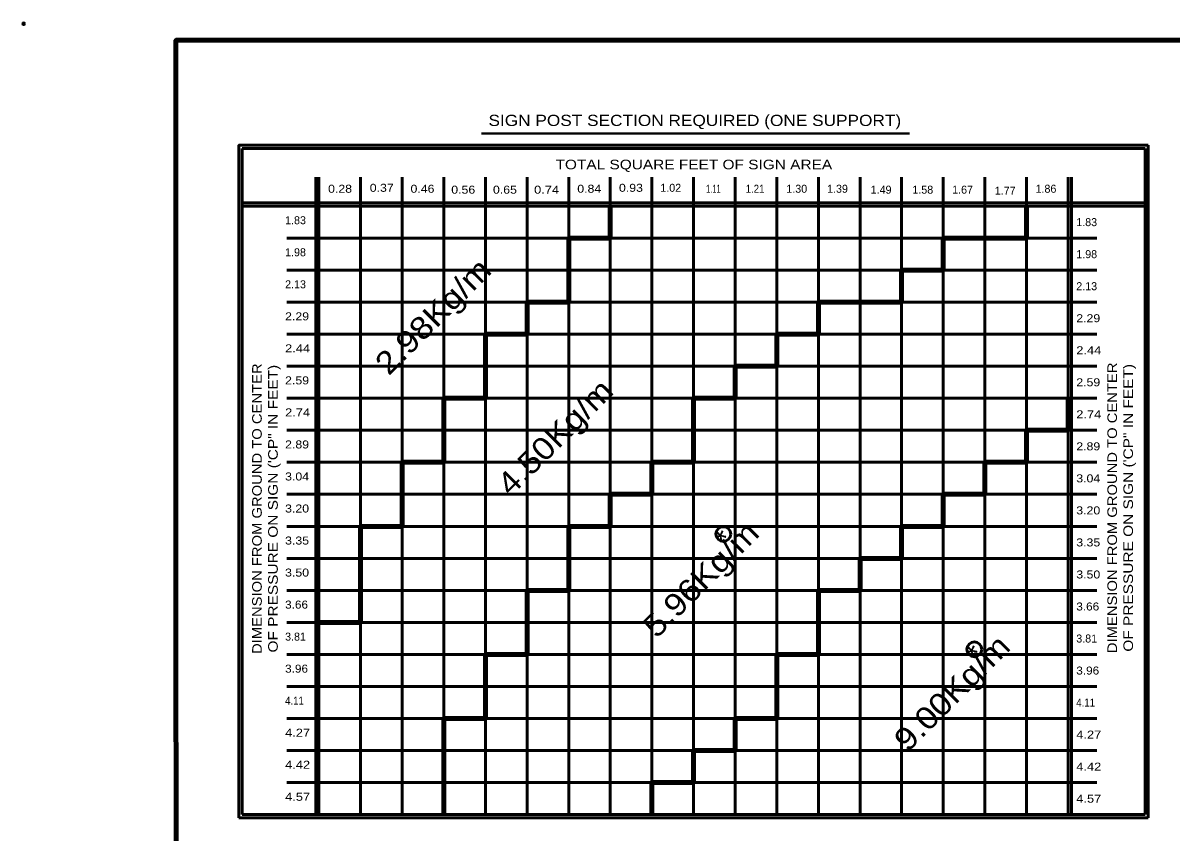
# Model space of a CAD drawing. Extents: x -39 to 816, y -2 to 542.
# Drawn here: x -39.3 to 390.9, y 239.3 to 542.4 of the extents above; entities that cross this region are included whole.
import ezdxf
from ezdxf.enums import TextEntityAlignment as Align

# ---------------------------------------------------------------- set-up
doc = ezdxf.new("R2010")
doc.units = 0
doc.header["$LTSCALE"] = 1.2
doc.header["$PDMODE"] = 32
doc.header["$PDSIZE"] = 0.6
doc.layers.add('1', color=7, linetype='Continuous', lineweight=53)

msp = doc.modelspace()

# ---------------------------------------------------------------- linework, layer by layer
at = {"layer": '1', "lineweight": 40}
msp.add_line((132.557, 500.998), (292.88, 500.998), dxfattribs=at)
at = {"layer": '1'}
for p, q in [((42.794, 495.432), (42.794, 245.832)), ((381.194, 495.432), (42.794, 495.432)), ((381.194, 245.832), (381.194, 495.432)), ((382.394, 244.632), (382.394, 496.632)), ((70.394, 484.632), (70.394, 245.832)), ((71.594, 484.632), (71.594, 245.832)), ((87.194, 484.632), (87.194, 475.032)), ((102.794, 484.632), (102.794, 377.832)), ((118.394, 484.632), (118.394, 401.832)), ((133.994, 484.632), (133.994, 425.832)), ((149.594, 484.632), (149.594, 437.832)), ((165.194, 484.632), (165.194, 461.832)), ((180.793, 484.632), (180.793, 473.832)), ((196.394, 484.632), (196.394, 377.832)), ((211.994, 484.632), (211.994, 401.832)), ((227.594, 484.632), (227.594, 413.832)), ((243.194, 484.632), (243.194, 425.832)), ((258.793, 484.632), (258.793, 437.832)), ((274.394, 484.632), (274.394, 341.832)), ((289.994, 484.632), (289.994, 449.832)), ((305.594, 484.632), (305.594, 461.832)), ((321.194, 484.632), (321.194, 377.832)), ((336.793, 484.632), (336.793, 473.832)), ((352.394, 401.832), (352.394, 484.632)), ((353.594, 245.832), (353.594, 484.632)), ((381.194, 475.032), (42.794, 475.032)), ((381.194, 473.832), (42.794, 473.832)), ((87.194, 475.032), (87.194, 353.832)), ((59.594, 461.832), (70.394, 461.832)), ((70.394, 461.832), (165.194, 461.832)), ((180.793, 461.832), (305.594, 461.832)), ((180.793, 461.832), (180.793, 365.832)), ((336.793, 461.832), (363.194, 461.832)), ((336.793, 461.832), (336.793, 389.832)), ((59.594, 449.832), (289.994, 449.832)), ((305.594, 449.832), (363.194, 449.832)), ((305.594, 449.832), (305.594, 365.832)), ((59.594, 437.832), (149.594, 437.832)), ((165.194, 437.832), (258.793, 437.832)), ((165.194, 437.832), (165.194, 353.832)), ((289.994, 437.832), (363.194, 437.832)), ((289.994, 437.832), (289.994, 353.832)), ((59.594, 425.832), (133.994, 425.832)), ((149.594, 425.832), (243.194, 425.832)), ((149.594, 425.832), (149.594, 329.832)), ((258.793, 425.832), (363.194, 425.832)), ((258.793, 425.832), (258.793, 329.832)), ((59.594, 413.832), (227.594, 413.832)), ((243.194, 413.832), (363.194, 413.832)), ((243.194, 413.832), (243.194, 305.832)), ((59.594, 401.832), (118.394, 401.832)), ((133.994, 401.832), (211.994, 401.832)), ((133.994, 401.832), (133.994, 305.832)), ((227.594, 401.832), (363.194, 401.832)), ((227.594, 401.832), (227.594, 281.832)), ((59.594, 389.832), (336.793, 389.832)), ((352.394, 245.832), (352.394, 389.832)), ((352.394, 389.832), (363.194, 389.832)), ((59.594, 377.832), (102.794, 377.832)), ((118.394, 377.832), (196.394, 377.832)), ((118.394, 377.832), (118.394, 281.832)), ((211.994, 377.832), (321.194, 377.832)), ((211.994, 377.832), (211.994, 269.832)), ((336.793, 377.832), (336.793, 245.832)), ((59.594, 365.832), (180.793, 365.832)), ((196.394, 365.832), (305.594, 365.832)), ((196.394, 365.832), (196.394, 257.832)), ((321.194, 365.832), (321.194, 245.832)), ((321.194, 365.832), (363.194, 365.832)), ((59.594, 353.832), (71.594, 353.832)), ((71.594, 353.832), (87.194, 353.832)), ((102.794, 353.832), (102.794, 245.832)), ((102.794, 353.832), (165.194, 353.832)), ((180.793, 353.832), (180.793, 245.832)), ((180.793, 353.832), (289.994, 353.832)), ((305.594, 353.832), (305.594, 245.832)), ((305.594, 353.832), (363.194, 353.832)), ((59.594, 341.832), (274.394, 341.832)), ((289.994, 341.832), (289.994, 245.832)), ((289.994, 341.832), (363.194, 341.832)), ((59.594, 329.832), (149.594, 329.832)), ((165.194, 329.832), (165.194, 245.832)), ((165.194, 329.832), (258.793, 329.832)), ((274.394, 329.832), (274.394, 245.832)), ((274.394, 329.832), (363.194, 329.832)), ((59.594, 317.832), (71.594, 317.832)), ((87.194, 317.832), (363.194, 317.832)), ((87.194, 317.832), (87.194, 245.832)), ((59.594, 305.832), (133.994, 305.832)), ((149.594, 305.832), (149.594, 245.832)), ((149.594, 305.832), (243.194, 305.832)), ((258.793, 305.832), (258.793, 245.832)), ((258.793, 305.832), (363.194, 305.832)), ((59.594, 293.832), (363.194, 293.832)), ((59.594, 281.832), (118.394, 281.832)), ((133.994, 281.832), (133.994, 245.832)), ((133.994, 281.832), (227.594, 281.832)), ((243.194, 281.832), (243.194, 245.832)), ((243.194, 281.832), (363.194, 281.832)), ((59.594, 269.832), (211.994, 269.832)), ((227.594, 269.832), (227.594, 245.832)), ((227.594, 269.832), (363.194, 269.832)), ((59.594, 257.832), (196.394, 257.832)), ((211.994, 257.832), (211.994, 245.832)), ((211.994, 257.832), (363.194, 257.832)), ((42.794, 245.832), (381.194, 245.832)), ((41.593, 244.632), (382.394, 244.632))]:
    msp.add_line(p, q, dxfattribs=at)
at = {"layer": '1', "lineweight": 200}
for p, q in [((180.793, 473.832), (180.793, 461.832)), ((336.793, 473.832), (336.793, 461.832)), ((165.194, 461.832), (165.194, 437.832)), ((165.194, 461.832), (180.793, 461.832)), ((305.594, 461.832), (336.793, 461.832)), ((305.594, 461.832), (305.594, 449.832)), ((289.994, 449.832), (305.594, 449.832)), ((289.994, 449.832), (289.994, 437.832)), ((149.594, 437.832), (149.594, 425.832)), ((149.594, 437.832), (165.194, 437.832)), ((258.793, 437.832), (289.994, 437.832)), ((258.793, 437.832), (258.793, 425.832)), ((133.994, 425.832), (133.994, 401.832)), ((133.994, 425.832), (149.594, 425.832)), ((243.194, 425.832), (258.793, 425.832)), ((243.194, 425.832), (243.194, 413.832)), ((227.594, 413.832), (243.194, 413.832)), ((227.594, 413.832), (227.594, 401.832)), ((118.394, 401.832), (118.394, 377.832)), ((118.394, 401.832), (133.994, 401.832)), ((211.994, 401.832), (227.594, 401.832)), ((211.994, 401.832), (211.994, 377.832)), ((352.394, 389.832), (352.394, 401.832)), ((336.793, 389.832), (352.394, 389.832)), ((336.793, 389.832), (336.793, 377.832)), ((102.794, 377.832), (118.394, 377.832)), ((102.794, 377.832), (102.794, 353.832)), ((196.394, 377.832), (211.994, 377.832)), ((196.394, 377.832), (196.394, 365.832)), ((321.194, 377.832), (336.793, 377.832)), ((321.194, 377.832), (321.194, 365.832)), ((180.793, 365.832), (196.394, 365.832)), ((180.793, 365.832), (180.793, 353.832)), ((305.594, 365.832), (321.194, 365.832)), ((305.594, 365.832), (305.594, 353.832)), ((87.194, 353.832), (87.194, 317.832)), ((87.194, 353.832), (102.794, 353.832)), ((165.194, 353.832), (180.793, 353.832)), ((165.194, 353.832), (165.194, 329.832)), ((289.994, 353.832), (305.594, 353.832)), ((289.994, 353.832), (289.994, 341.832)), ((274.394, 341.832), (289.994, 341.832)), ((274.394, 341.832), (274.394, 329.832)), ((149.594, 329.832), (165.194, 329.832)), ((149.594, 329.832), (149.594, 305.832)), ((258.793, 329.832), (274.394, 329.832)), ((258.793, 329.832), (258.793, 305.832)), ((71.594, 317.832), (87.194, 317.832)), ((133.994, 305.832), (149.594, 305.832)), ((133.994, 305.832), (133.994, 281.832)), ((243.194, 305.832), (258.793, 305.832)), ((243.194, 305.832), (243.194, 281.832)), ((118.394, 281.832), (133.994, 281.832)), ((118.394, 281.832), (118.394, 245.832)), ((227.594, 281.832), (243.194, 281.832)), ((227.594, 281.832), (227.594, 269.832)), ((211.994, 269.832), (227.594, 269.832)), ((211.994, 269.832), (211.994, 257.832)), ((196.394, 257.832), (196.394, 245.832)), ((196.394, 257.832), (211.994, 257.832))]:
    msp.add_line(p, q, dxfattribs=at)
at = {"layer": '1', "lineweight": 158}
msp.add_lwpolyline([(809.673, 536.027), (17.973, 535.927), (18.073, 9.927)], dxfattribs=at)
at = {"layer": '1'}
for points in [[(382.394, 496.632), (41.593, 496.632), (41.593, 244.632)], [(336.793, 377.832), (353.594, 377.832), (363.194, 377.832)]]:
    msp.add_lwpolyline(points, dxfattribs=at)
for centre in [(223.176, 350.937), (317.238, 307.739)]:
    msp.add_circle(centre, 2.772, dxfattribs=at)
msp.add_point((-39.027, 542.127), dxfattribs=at)

# ---------------------------------------------------------------- texts
for s, height, width, p in [('SIGN POST SECTION REQUIRED (ONE SUPPORT)', 4.2, 1.15, (212.466, 503.828)), ('TOTAL SQUARE FEET OF SIGN AREA', 3.6, 1.2, (212.105, 487.599)), ('0.37', 3, 1.15, (95.138, 479.173)), ('0.93', 3, 1.15, (188.532, 479.173)), ('0.28', 3, 1.15, (79.513, 478.818)), ('0.46', 3, 1.15, (110.408, 478.818)), ('0.56', 3, 1.15, (125.678, 478.463)), ('0.65', 3, 1.15, (141.303, 478.463)), ('0.74', 3, 1.2, (156.928, 478.463)), ('0.84', 3, 1.15, (172.908, 478.818)), ('1.11', 3, 0.7, (219.427, 478.818)), ('1.21', 3, 0.9, (235.052, 478.818))]:
    msp.add_text(s, height=height, dxfattribs=dict(at, width=width)).set_placement(p, align=Align.CENTER)
for s, p in [('1.02', (203.447, 479.173)), ('1.30', (250.677, 478.818)), ('1.39', (265.947, 478.818)), ('1.49', (282.282, 478.463)), ('1.58', (297.907, 478.463)), ('1.67', (312.821, 478.463)), ('1.77', (328.802, 478.108)), ('1.86', (344.071, 478.818))]:
    msp.add_text(s, height=3, dxfattribs=at).set_placement(p, align=Align.CENTER)
for s, p in [('1.83', (58.917, 467.017)), ('1.83', (355.435, 466.307)), ('1.98', (58.917, 455.017)), ('1.98', (355.435, 454.307)), ('2.13', (58.917, 443.017)), ('2.13', (355.435, 442.307)), ('3.81', (58.917, 311.017)), ('3.81', (355.435, 310.307))]:
    msp.add_text(s, height=3, dxfattribs=at).set_placement(p)
for s, height, rotation, width, p in [('2.98Kg/m', 8.4, 45, 1.15, (117.295, 429.573)), ('DIMENSION FROM GROUND TO CENTER', 3.6, 90, 1.15, (50.171, 360.458)), ('OF PRESSURE ON SIGN (\'CP" IN FEET)', 3.6, 90, 1.2, (56.171, 360.458)), ('DIMENSION FROM GROUND TO CENTER', 3.6, 90, 1.15, (370.703, 360.77)), ('OF PRESSURE ON SIGN (\'CP" IN FEET)', 3.6, 90, 1.2, (376.703, 360.77)), ('4.50Kg/m', 8.4, 45, 1.15, (163.004, 384.336)), ('5.96Kg/m', 8.4, 45, 1.15, (217.708, 331.073)), ('9.00Kg/m', 8.4, 45, 1.15, (311.8, 288.511))]:
    msp.add_text(s, height=height, rotation=rotation, dxfattribs=dict(at, width=width)).set_placement(p, align=Align.CENTER)
for s, width, p in [('2.29', 1.15, (58.917, 431.017)), ('2.29', 1.15, (355.435, 430.307)), ('2.44', 1.2, (58.917, 419.017)), ('2.44', 1.2, (355.435, 418.307)), ('2.59', 1.15, (58.917, 407.017)), ('2.59', 1.15, (355.435, 406.307)), ('2.74', 1.2, (58.917, 395.017)), ('2.74', 1.2, (355.435, 394.307)), ('2.89', 1.15, (58.917, 383.017)), ('2.89', 1.15, (355.435, 382.307)), ('3.04', 1.15, (58.917, 371.017)), ('3.04', 1.15, (355.435, 370.307)), ('3.20', 1.15, (58.917, 359.017)), ('3.20', 1.15, (355.435, 358.307)), ('3.35', 1.15, (58.917, 347.017)), ('3.35', 1.15, (355.435, 346.307)), ('3.50', 1.15, (58.917, 335.017)), ('3.50', 1.15, (355.435, 334.307)), ('3.66', 1.1, (58.917, 323.017)), ('3.66', 1.1, (355.435, 322.307)), ('3.96', 1.1, (58.917, 299.017)), ('3.96', 1.1, (355.435, 298.307)), ('4.11', 0.9, (58.917, 287.017)), ('4.11', 0.9, (355.435, 286.307)), ('4.27', 1.2, (58.917, 275.017)), ('4.27', 1.2, (355.435, 274.307)), ('4.42', 1.2, (58.917, 263.017)), ('4.42', 1.2, (355.435, 262.307)), ('4.57', 1.2, (58.917, 251.017)), ('4.57', 1.2, (355.435, 250.307))]:
    msp.add_text(s, height=3, dxfattribs=dict(at, width=width)).set_placement(p)
for p in [(226.422, 345.996), (320.593, 302.897)]:
    msp.add_text('*', height=8.4, rotation=45, dxfattribs=at).set_placement(p, align=Align.CENTER)

doc.saveas('drawing.dxf')
